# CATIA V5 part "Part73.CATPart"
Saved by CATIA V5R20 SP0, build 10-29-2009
Part number: FA 053000-1
Revision: ANY
Definition: UNKNOWN
Nomenclature: FA 053000-1
Source: Unknown
Bounding box of the stored display mesh (mm): x -1.9 to 1.9, y -1.1 to 2.45, z -1.9 to 1.9
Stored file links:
  C:\Users\Utente\Desktop\IO LAVORO\3D X SITO CF\CUMSA\3D files FA\FA 053004-20\Part73.CATPart

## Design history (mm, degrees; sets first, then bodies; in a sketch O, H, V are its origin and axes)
Body1 "Cortar-Extruir1" (main body)
  Solid1: solid without history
